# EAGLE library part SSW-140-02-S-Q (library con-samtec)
THROUGH-HOLE .025" SQ POST SOCKET Source: Samtec SSW.pdf
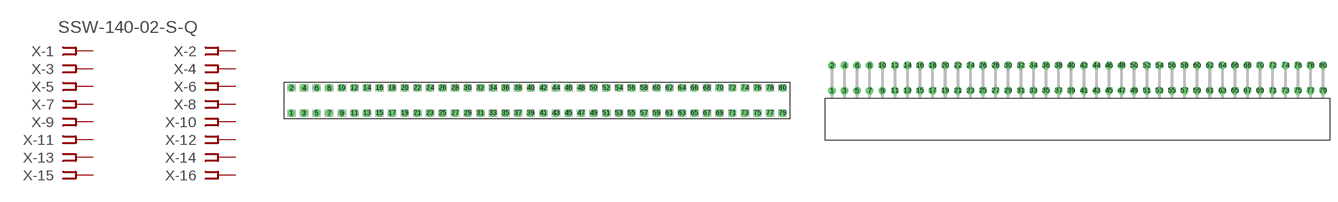
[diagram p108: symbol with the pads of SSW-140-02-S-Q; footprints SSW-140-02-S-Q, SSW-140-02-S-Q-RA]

Designator prefix X; gates -1=FPINV -2=FPIN -3=FPIN -4=FPIN -5=FPIN -6=FPIN -7=FPIN -8=FPIN -9=FPIN -10=FPIN -11=FPIN -12=FPIN -13=FPIN -14=FPIN -15=FPIN -16=FPIN -17=FPIN -18=FPIN -19=FPIN -20=FPIN -21=FPIN -22=FPIN -23=FPIN -24=FPIN -25=FPIN -26=FPIN -27=FPIN -28=FPIN -29=FPIN -30=FPIN -31=FPIN -32=FPIN -33=FPIN -34=FPIN -35=FPIN -36=FPIN -37=FPIN -38=FPIN -39=FPIN -40=FPIN -41=FPIN -42=FPIN -43=FPIN -44=FPIN -45=FPIN -46=FPIN -47=FPIN -48=FPIN -49=FPIN -50=FPIN -51=FPIN -52=FPIN -53=FPIN -54=FPIN -55=FPIN -56=FPIN -57=FPIN -58=FPIN -59=FPIN -60=FPIN -61=FPIN -62=FPIN -63=FPIN -64=FPIN -65=FPIN -66=FPIN -67=FPIN -68=FPIN -69=FPIN -70=FPIN -71=FPIN -72=FPIN -73=FPIN -74=FPIN -75=FPIN -76=FPIN -77=FPIN -78=FPIN -79=FPIN -80=FPIN

## SSW-140-02-S-Q (MPN: SSW-140-02-S-Q; OC_FARNELL: unknown; OC_NEWARK: 83P1365)  [SSW-140-02-S-Q]
1  -1:1  pas
2  -2:1  pas
3  -3:1  pas
4  -4:1  pas
5  -5:1  pas
6  -6:1  pas
7  -7:1  pas
8  -8:1  pas
9  -9:1  pas
10  -10:1  pas
11  -11:1  pas
12  -12:1  pas
13  -13:1  pas
14  -14:1  pas
15  -15:1  pas
16  -16:1  pas
17  -17:1  pas
18  -18:1  pas
19  -19:1  pas
20  -20:1  pas
21  -21:1  pas
22  -22:1  pas
23  -23:1  pas
24  -24:1  pas
25  -25:1  pas
26  -26:1  pas
27  -27:1  pas
28  -28:1  pas
29  -29:1  pas
30  -30:1  pas
31  -31:1  pas
32  -32:1  pas
33  -33:1  pas
34  -34:1  pas
35  -35:1  pas
36  -36:1  pas
37  -37:1  pas
38  -38:1  pas
39  -39:1  pas
40  -40:1  pas
41  -41:1  pas
42  -42:1  pas
43  -43:1  pas
44  -44:1  pas
45  -45:1  pas
46  -46:1  pas
47  -47:1  pas
48  -48:1  pas
49  -49:1  pas
50  -50:1  pas
51  -51:1  pas
52  -52:1  pas
53  -53:1  pas
54  -54:1  pas
55  -55:1  pas
56  -56:1  pas
57  -57:1  pas
58  -58:1  pas
59  -59:1  pas
60  -60:1  pas
61  -61:1  pas
62  -62:1  pas
63  -63:1  pas
64  -64:1  pas
65  -65:1  pas
66  -66:1  pas
67  -67:1  pas
68  -68:1  pas
69  -69:1  pas
70  -70:1  pas
71  -71:1  pas
72  -72:1  pas
73  -73:1  pas
74  -74:1  pas
75  -75:1  pas
76  -76:1  pas
77  -77:1  pas
78  -78:1  pas
79  -79:1  pas
80  -80:1  pas

## SSW-140-02-S-QRA (MPN: SSW-140-02-S-Q-RA; OC_FARNELL: unknown; OC_NEWARK: 83P1366)  [SSW-140-02-S-Q-RA]
Pads as for SSW-140-02-S-Q

## Footprint SSW-140-02-S-Q (pad centres in mm)
THROUGH-HOLE .025" SQ POST SOCKET Source: Samtec SSW.pdf
drill 1 pad 1.5 octagon: 1 -49.53,-2.54; 2 -49.53,2.54; 3 -46.99,-2.54; 4 -46.99,2.54; 5 -44.45,-2.54; 6 -44.45,2.54; 7 -41.91,-2.54; 8 -41.91,2.54; 9 -39.37,-2.54; 10 -39.37,2.54; 11 -36.83,-2.54; 12 -36.83,2.54; 13 -34.29,-2.54; 14 -34.29,2.54; 15 -31.75,-2.54; 16 -31.75,2.54; 17 -29.21,-2.54; 18 -29.21,2.54; 19 -26.67,-2.54; 20 -26.67,2.54; 21 -24.13,-2.54; 22 -24.13,2.54; 23 -21.59,-2.54; 24 -21.59,2.54; 25 -19.05,-2.54; 26 -19.05,2.54; 27 -16.51,-2.54; 28 -16.51,2.54; 29 -13.97,-2.54; 30 -13.97,2.54; 31 -11.43,-2.54; 32 -11.43,2.54; 33 -8.89,-2.54; 34 -8.89,2.54; 35 -6.35,-2.54; 36 -6.35,2.54; 37 -3.81,-2.54; 38 -3.81,2.54; 39 -1.27,-2.54; 40 -1.27,2.54; 41 1.27,-2.54; 42 1.27,2.54; 43 3.81,-2.54; 44 3.81,2.54; 45 6.35,-2.54; 46 6.35,2.54; 47 8.89,-2.54; 48 8.89,2.54; 49 11.43,-2.54; 50 11.43,2.54; 51 13.97,-2.54; 52 13.97,2.54; 53 16.51,-2.54; 54 16.51,2.54; 55 19.05,-2.54; 56 19.05,2.54; 57 21.59,-2.54; 58 21.59,2.54; 59 24.13,-2.54; 60 24.13,2.54; 61 26.67,-2.54; 62 26.67,2.54; 63 29.21,-2.54; 64 29.21,2.54; 65 31.75,-2.54; 66 31.75,2.54; 67 34.29,-2.54; 68 34.29,2.54; 69 36.83,-2.54; 70 36.83,2.54; 71 39.37,-2.54; 72 39.37,2.54; 73 41.91,-2.54; 74 41.91,2.54; 75 44.45,-2.54; 76 44.45,2.54; 77 46.99,-2.54; 78 46.99,2.54; 79 49.53,-2.54; 80 49.53,2.54

## Footprint SSW-140-02-S-Q-RA (pad centres in mm)
THROUGH-HOLE .025" SQ POST SOCKET Source: Samtec SSW.pdf
drill 1 pad 1.5 octagon: 1 -49.53,1.524; 2 -49.53,6.604; 3 -46.99,1.524; 4 -46.99,6.604; 5 -44.45,1.524; 6 -44.45,6.604; 7 -41.91,1.524; 8 -41.91,6.604; 9 -39.37,1.524; 10 -39.37,6.604; 11 -36.83,1.524; 12 -36.83,6.604; 13 -34.29,1.524; 14 -34.29,6.604; 15 -31.75,1.524; 16 -31.75,6.604; 17 -29.21,1.524; 18 -29.21,6.604; 19 -26.67,1.524; 20 -26.67,6.604; 21 -24.13,1.524; 22 -24.13,6.604; 23 -21.59,1.524; 24 -21.59,6.604; 25 -19.05,1.524; 26 -19.05,6.604; 27 -16.51,1.524; 28 -16.51,6.604; 29 -13.97,1.524; 30 -13.97,6.604; 31 -11.43,1.524; 32 -11.43,6.604; 33 -8.89,1.524; 34 -8.89,6.604; 35 -6.35,1.524; 36 -6.35,6.604; 37 -3.81,1.524; 38 -3.81,6.604; 39 -1.27,1.524; 40 -1.27,6.604; 41 1.27,1.524; 42 1.27,6.604; 43 3.81,1.524; 44 3.81,6.604; 45 6.35,1.524; 46 6.35,6.604; 47 8.89,1.524; 48 8.89,6.604; 49 11.43,1.524; 50 11.43,6.604; 51 13.97,1.524; 52 13.97,6.604; 53 16.51,1.524; 54 16.51,6.604; 55 19.05,1.524; 56 19.05,6.604; 57 21.59,1.524; 58 21.59,6.604; 59 24.13,1.524; 60 24.13,6.604; 61 26.67,1.524; 62 26.67,6.604; 63 29.21,1.524; 64 29.21,6.604; 65 31.75,1.524; 66 31.75,6.604; 67 34.29,1.524; 68 34.29,6.604; 69 36.83,1.524; 70 36.83,6.604; 71 39.37,1.524; 72 39.37,6.604; 73 41.91,1.524; 74 41.91,6.604; 75 44.45,1.524; 76 44.45,6.604; 77 46.99,1.524; 78 46.99,6.604; 79 49.53,1.524; 80 49.53,6.604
